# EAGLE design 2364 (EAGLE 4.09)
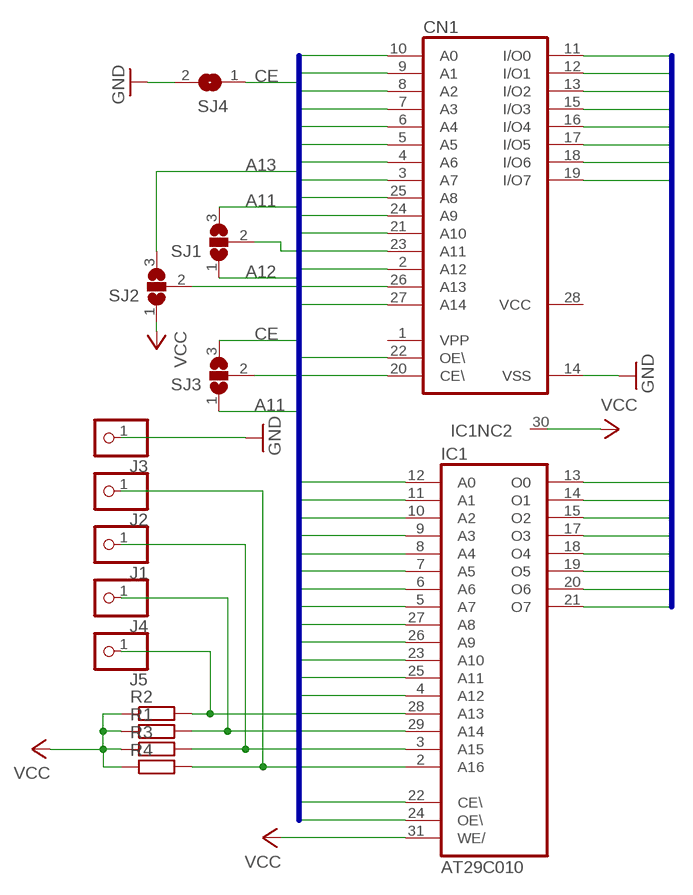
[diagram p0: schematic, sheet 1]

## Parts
CN1  27C256AG  [DIL28-6]
IC1  AT29C010  AM29F010P  [DIL32-3]
J1  PINHD-1X1  [1X01]
J2  PINHD-1X1  [1X01]
J3  PINHD-1X1  [1X01]
J4  PINHD-1X1  [1X01]
J5  PINHD-1X1  [1X01]
R1  R-EU_M0805  [M0805]
R2  R-EU_M0805  [M0805]
R3  R-EU_M0805  [M0805]
R4  R-EU_M0805  [M0805]
SJ1  SJ2W  [SJ_2]
SJ2  SJ2W  [SJ_2]
SJ3  SJ2W  [SJ_2]
SJ4  SJ  [SJ]

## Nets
A0: CN1.10(A0) IC1.12(A0)
A1: CN1.9(A1) IC1.11(A1)
A2: CN1.8(A2) IC1.10(A2)
A3: CN1.7(A3) IC1.9(A3)
A4: CN1.6(A4) IC1.8(A4)
A5: CN1.5(A5) IC1.7(A5)
A6: CN1.4(A6) IC1.6(A6)
A7: CN1.3(A7) IC1.5(A7)
A8: CN1.25(A8) IC1.27(A8)
A9: CN1.24(A9) IC1.26(A9)
A10: CN1.21(A10) IC1.23(A10)
A11: IC1.25(A11) SJ1.3 SJ3.1
A12: CN1.2(A12) IC1.4(A12) SJ1.1
A13: IC1.28(A13) J5.1 R2.2 SJ2.3
A14: CN1.27(A14) IC1.29(A14) J4.1 R1.2
CE: IC1.22(CE\) SJ3.3 SJ4.1
D0: CN1.11(I/O0) IC1.13(O0)
D1: CN1.12(I/O1) IC1.14(O1)
D2: CN1.13(I/O2) IC1.15(O2)
D3: CN1.15(I/O3) IC1.17(O3)
D4: CN1.16(I/O4) IC1.18(O4)
D5: CN1.17(I/O5) IC1.19(O5)
D6: CN1.18(I/O6) IC1.20(O6)
D7: CN1.19(I/O7) IC1.21(O7)
GND: CN1.14(VSS) J3.1 SJ4.2
N$1: IC1.2(A16) J2.1 R4.2
N$2: IC1.3(A15) J1.1 R3.2
N$3: CN1.23(A11) SJ1.2
N$4: CN1.26(A13) SJ2.2
N$5: CN1.20(CE\) SJ3.2
OE: CN1.22(OE\) IC1.24(OE\)
VCC: IC1.30(NC) IC1.31(WE/) R1.1 R2.1 R3.1 R4.1 SJ2.1
Unconnected: CN1.1(VPP) IC1.1(NC)

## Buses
D[0..7]
A[0..14],OE,CE

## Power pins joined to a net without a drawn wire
GND: IC1.16(GND)
VCC: CN1.28(VCC) IC1.32(VCC)

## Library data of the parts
CN1 = memory-hitachi:27C256AG: MEMORY
IC1 = am29-memory:AM29F010*: 1-Megabit FLASH MEMORY (128 K x 8 bit) 5 V-only
J1-J5 = pinhead:PINHD-1X1: PIN HEADER
R1-R4 = rcl:R-EU_: RESISTOR, European symbol
SJ1-SJ3 = jumper:SJ2W: SMD solder JUMPER
SJ4 = jumper:SJ: SMD solder JUMPER

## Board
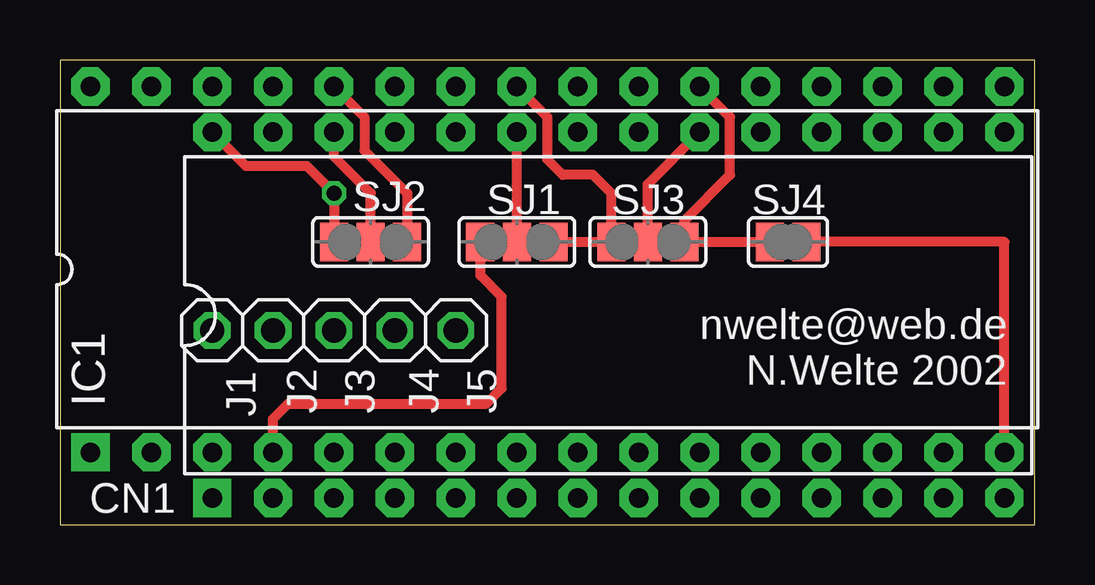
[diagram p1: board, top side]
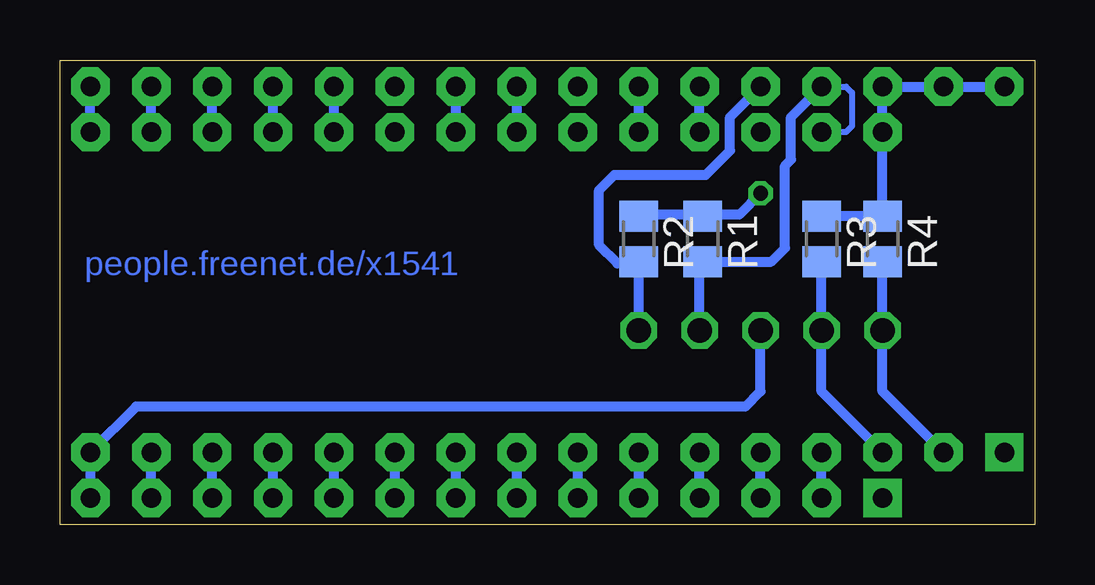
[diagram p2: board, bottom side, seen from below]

Size 40.63 x 19.36 mm. Coordinates in mm from the lower left corner, seen from the top.
Outline: 40.63,0 40.63,19.36 0,19.36 0,0 40.63,0
Copper layers used: Top, Bottom

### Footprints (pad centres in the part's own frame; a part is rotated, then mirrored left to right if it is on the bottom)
DIL28-6 = drill 0.813 pad 1.6 square: 1 -16.51,-7.62 | drill 0.813 pad 1.6 octagon: 2 -13.97,-7.62; 3 -11.43,-7.62; 4 -8.89,-7.62; 5 -6.35,-7.62; 6 -3.81,-7.62; 7 -1.27,-7.62; 8 1.27,-7.62; 9 3.81,-7.62; 10 6.35,-7.62; 11 8.89,-7.62; 12 11.43,-7.62; 13 13.97,-7.62; 14 16.51,-7.62; 15 16.51,7.62; 16 13.97,7.62; 17 11.43,7.62; 18 8.89,7.62; 19 6.35,7.62; 20 3.81,7.62; 21 1.27,7.62; 22 -1.27,7.62; 23 -3.81,7.62; 24 -6.35,7.62; 25 -8.89,7.62; 26 -11.43,7.62; 27 -13.97,7.62; 28 -16.51,7.62
DIL32-3 = drill 0.813 pad 1.6 square: 1 -19.05,-3.81 | drill 0.813 pad 1.6 octagon: 2 -16.51,-3.81; 3 -13.97,-3.81; 4 -11.43,-3.81; 5 -8.89,-3.81; 6 -6.35,-3.81; 7 -3.81,-3.81; 8 -1.27,-3.81; 9 1.27,-3.81; 10 3.81,-3.81; 11 6.35,-3.81; 12 8.89,-3.81; 13 11.43,-3.81; 14 13.97,-3.81; 15 16.51,-3.81; 16 19.05,-3.81; 17 19.05,11.43; 18 16.51,11.43; 19 13.97,11.43; 20 11.43,11.43; 21 8.89,11.43; 22 6.35,11.43; 23 3.81,11.43; 24 1.27,11.43; 25 -1.27,11.43; 26 -3.81,11.43; 27 -6.35,11.43; 28 -8.89,11.43; 29 -11.43,11.43; 30 -13.97,11.43; 31 -16.51,11.43; 32 -19.05,11.43
1X01 = drill 1.016 octagon: 1 0,0
M0805 = smd 1.3 x 1.6: 1 -0.95,0; 2 0.95,0
SJ_2 = smd 1.168 x 1.6: 1 -1.524,0; 2 0,0; 3 1.524,0
SJ = smd 1.168 x 1.6: 1 -0.762,0; 2 0.762,0

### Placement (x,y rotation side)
CN1  22.85,8.72 0 top
IC1  20.31,6.82 0 top
J1  8.88,8.09 90 top
J2  6.35,8.09 90 top
J3  11.43,8.09 90 top
J4  13.96,8.09 90 top
J5  16.5,8.09 90 top
R1  13.84,11.9 270 bottom
R2  16.5,11.9 270 bottom
R3  8.88,11.9 270 bottom
R4  6.35,11.9 270 bottom
SJ1  19.04,11.77 0 top
SJ2  12.95,11.77 0 top
SJ3  24.51,11.77 0 top
SJ4  30.35,11.77 0 top

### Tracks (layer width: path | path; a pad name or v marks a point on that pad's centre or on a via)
A0
  Bottom 0.406: CN1.10 IC1.12
A1
  Bottom 0.406: CN1.9 IC1.11
A2
  Bottom 0.406: CN1.8 IC1.10
A3
  Bottom 0.406: CN1.7 IC1.9
A4
  Bottom 0.406: CN1.6 IC1.8
A5
  Bottom 0.406: CN1.5 IC1.7
A6
  Bottom 0.406: CN1.4 IC1.6
A7
  Bottom 0.406: CN1.3 IC1.5
A8
  Bottom 0.406: CN1.25 IC1.27
A9
  Bottom 0.406: CN1.24 IC1.26
A10
  Bottom 0.406: CN1.21 IC1.23
A11
  Top 0.406: SJ1.3 SJ3.1 22.98,13.8 22.22,14.57 20.95,14.57 20.31,15.2 20.31,16.98 IC1.25
A12
  Top 0.406: SJ1.1 17.52,10.38 18.41,9.49 18.41,5.68 17.77,5.04 9.52,5.04 8.88,4.41 IC1.4
  Bottom 0.406: CN1.2 IC1.4
A13
  Top 0.406: SJ2.3 14.47,13.8 12.7,15.58 12.7,16.98 IC1.28
  Bottom 0.406: 16.5,11.01 R2.2 16.5,10.88 | J5.1 16.5,10.88 | IC1.28 12.7,16.98 12.7,15.58 13.71,14.57 17.52,14.57 18.16,13.93 18.16,11.65 17.39,10.88 16.5,10.88
A14
  Bottom 0.254: CN1.27 7.87,16.34 7.62,16.6 7.62,18 7.87,18.25 IC1.29
  Bottom 0.406: R1.2 13.84,11.01 | J4.1 13.96,10.95 R1.2 | R1.2 10.98,10.95 10.41,11.52 10.41,14.95 10.16,15.2 10.16,16.98 IC1.29
CE
  Top 0.406: IC1.22 27.93,16.98 27.93,14.57 26.03,12.66 SJ3.3 SJ4.1
D0
  Bottom 0.406: CN1.11 IC1.13
D1
  Bottom 0.406: CN1.12 IC1.14
D2
  Bottom 0.406: CN1.13 IC1.15
D3
  Bottom 0.406: CN1.15 IC1.17
D4
  Bottom 0.406: CN1.16 IC1.18
D5
  Bottom 0.406: CN1.17 IC1.19
D6
  Bottom 0.406: CN1.18 IC1.20
D7
  Bottom 0.406: CN1.19 IC1.21
GND
  Top 0.406: SJ4.2 39.37,11.77 IC1.16
  Bottom 0.406: J3.1 11.43,5.55 12.06,4.92 37.46,4.92 IC1.16 CN1.14
N$1
  Bottom 0.406: J2.1 R4.2 J2.1 | IC1.2 6.35,5.55 J2.1
N$2
  Bottom 0.406: R3.2 8.88,8.22 J1.1 8.88,5.55 IC1.3
N$3
  Top 0.406: SJ1.2 CN1.23
N$4
  Top 0.406: SJ2.2 12.95,13.8 11.43,15.33 CN1.26
N$5
  Top 0.406: SJ3.2 24.51,14.19 CN1.20
OE
  Bottom 0.406: CN1.22 IC1.24
VCC  (via drill 0.61)
  Top 0.406: SJ2.1 v11.43,13.8 10.28,14.95 7.74,14.95 CN1.28
  Bottom 0.406: IC1.32 IC1.31 IC1.30 CN1.28 6.35,12.92 | R4.1 6.35,12.92 | 6.35,12.92 6.41,12.85 R3.1 8.88,12.79 | 13.84,12.79 R1.1 13.84,12.92 | R2.1 16.5,12.92 13.84,12.92 | v11.43,13.8 12.31,12.92 13.84,12.92

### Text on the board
Bottom: people.freenet.de/x1541
tNames: nwelte@web.de | N.Welte 2002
